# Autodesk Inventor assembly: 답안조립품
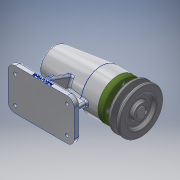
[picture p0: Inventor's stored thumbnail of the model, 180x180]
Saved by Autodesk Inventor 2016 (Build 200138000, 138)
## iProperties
Created: 2018-09
Part Number: 답안조립품
Material: 일반
Document SubType Name: Assembly
Designer: CAMTIC
Author: CAMTIC
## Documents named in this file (12)
- C:\Users\CAMTIC\Desktop\480907V1024\답안조립품.iam
- C:\Users\CAMTIC\Desktop\480907V1024\본체.ipt
- C:\Users\CAMTIC\Desktop\480907V1024\V벨트풀리.ipt
- C:\Users\CAMTIC\Desktop\480907V1024\멈춤나사 M3.ipt
- C:\Users\CAMTIC\Desktop\480907V1024\베어링 6004.ipt
- C:\Users\CAMTIC\Desktop\480907V1024\베어링 51202.ipt
- C:\Users\CAMTIC\Desktop\480907V1024\볼트 M4.ipt
- C:\Users\CAMTIC\Desktop\480907V1024\어댑터슬리브.ipt
- C:\Users\CAMTIC\Desktop\480907V1024\오일 실.ipt
- C:\Users\CAMTIC\Desktop\480907V1024\축.ipt
- C:\Users\CAMTIC\Desktop\480907V1024\커버.ipt
- C:\Users\CAMTIC\Desktop\480907V1024\키 5 x 5 x 16.ipt
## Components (1 placed, 1 different names)
1. V벨트풀리:1
